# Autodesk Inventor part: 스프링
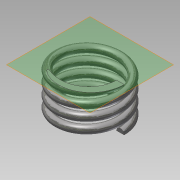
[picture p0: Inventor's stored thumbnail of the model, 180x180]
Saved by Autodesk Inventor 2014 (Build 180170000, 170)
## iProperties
Created: 2015-04
Part Number: 스프링
Material: 강철, 탄소
Document SubType Name: Modeling
Designer: Administrator
Density: 7.87 g/cm^3
Appearance: 반연마
Mass: 4.78743 g
Surface Area: 12.5262 cm^2
Volume: 0.608313 cm^3
Author: Administrator
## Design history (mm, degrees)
sketch "스케치1"
  geometry: L1 (0, 11.5)-(8, 11.5); L2 (8, 11.5)-(8, 0); L3 (8, 0)-(0, 0); L4 (0, 0)-(0, 11.5); C1 r 1 at (8, 0); 1 further point
  constraints: 8 end point, 2 coincident, 2 parallel, 1 centre point, 1 horizontal, 1 perpendicular
  dimensions: "d0" = 16 diameter of L2 L4; "d1" = 11.50049 distance between parallel lines of L1 L3 (derived); "d2" = 2 diameter of C1
feature "코일1" sketch "스케치1" pitch "d3" = 10; turns "d5" = 4; dims "d4" = 11.50049 (= d1), "d6" = 0, angle "d7" = 90 deg, angle "d8" = 90 deg, "d9" = 0, "d10" = 0
sketch "스케치2"
  geometry: L1 (-9, 0)-(-7, 0) reference; 1 further point
  constraints: 1 horizontal alignment
extrude "돌출1" cut sketch "스케치2" stored distance "d11" = 10; taper "d12" = 0 deg
node "작업 평면1"
sketch "스케치3"
  geometry: L1 (9, 0)-(7, 0) reference; 1 further point
  constraints: 1 horizontal alignment
extrude "돌출2" cut sketch "스케치3" stored distance "d13" = 10; taper "d14" = 0 deg
node "솔리드1"
node "절단 모서리 투영1"
node "절단 모서리 투영2"
